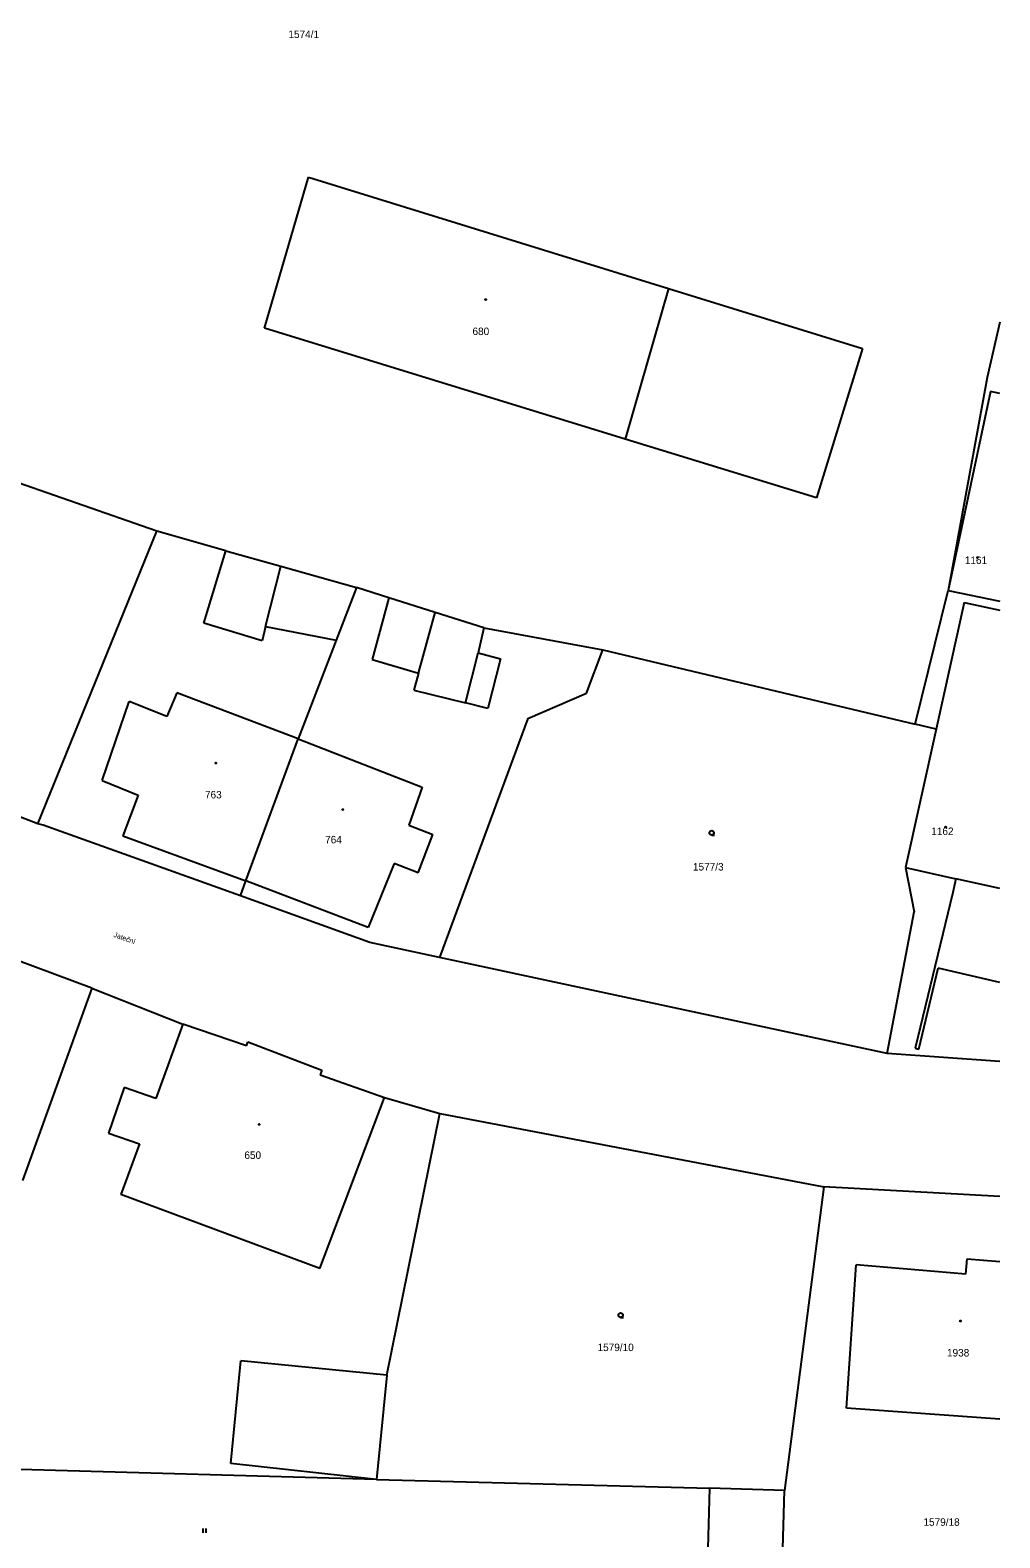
# Model space of a CAD drawing. Extents: x -866624 to -866276, y -1050208 to -1049940.
# Drawn here: x -866340.8 to -866276.1, y -1050100.7 to -1050000 of the extents above; entities that cross this region are included whole.
import ezdxf

# ---------------------------------------------------------------- set-up
doc = ezdxf.new("R2010")
doc.units = 0
for name, color, linetype in [('Default', 7, 'Continuous'), ('Hranice', 7, 'Continuous'), ('Hranice další', 7, 'Continuous'), ('Hranice-budov', 7, 'Continuous'), ('nazvy-ulic-tok', 7, 'Continuous'), ('Parcela-pozemkova', 7, 'Continuous'), ('Parcela-stavebni', 7, 'Continuous'), ('znacky-budov', 7, 'Continuous'), ('Znacky-kultury', 7, 'Continuous')]:
    doc.layers.add(name, color=color, linetype=linetype)

# ---------------------------------------------------------------- blocks, each defined once
blk = doc.blocks.new('p_zahr')
at = {"layer": 'Default'}
blk.add_line((0, -0.75), (0.99, -0.75), dxfattribs=at)
blk.add_circle((0, 0), 0.75, dxfattribs=at)
blk = doc.blocks.new('p_louka')
at = {"layer": 'Default'}
for p, q in [((-0.47, 0.72), (-0.47, -0.78)), ((0.53, 0.72), (0.53, -0.78))]:
    blk.add_line(p, q, dxfattribs=at)
blk = doc.blocks.new('s_zdena')
at = {"layer": 'Default'}
blk.add_circle((0, 0), 0.175, dxfattribs=at)
for start, end in [(0, 180), (180, 0)]:
    blk.add_arc((0, 0), 0.0875, start, end, dxfattribs=at)

msp = doc.modelspace()

# ---------------------------------------------------------------- linework, layer by layer
at = {"layer": 'Hranice'}
for p, q in [((-866325.18, -1050019.93), (-866322.25, -1050009.85)), ((-866322.25, -1050009.85), (-866298.21, -1050017.27)), ((-866298.21, -1050017.27), (-866285.24, -1050021.27)), ((-866276.08, -1050019.52), (-866276.93, -1050023.22)), ((-866301.1, -1050027.32), (-866325.18, -1050019.93)), ((-866285.24, -1050021.27), (-866288.32, -1050031.24)), ((-866276.93, -1050023.22), (-866279.54, -1050037.42)), ((-866276.7, -1050024.15), (-866279.54, -1050037.42)), ((-866276.08, -1050024.29), (-866276.7, -1050024.15)), ((-866332.37, -1050033.48), (-866353.36, -1050026.16)), ((-866288.32, -1050031.24), (-866301.1, -1050027.32)), ((-866340.32, -1050053.01), (-866332.37, -1050033.48)), ((-866327.75, -1050034.78), (-866332.37, -1050033.48)), ((-866327.75, -1050034.78), (-866324.08, -1050035.81)), ((-866324.08, -1050035.81), (-866319.04, -1050037.22)), ((-866319.04, -1050037.22), (-866320.39, -1050040.74)), ((-866316.88, -1050037.91), (-866319.04, -1050037.22)), ((-866313.78, -1050038.9), (-866316.88, -1050037.91)), ((-866281.73, -1050046.36), (-866279.54, -1050037.42)), ((-866279.54, -1050037.42), (-866276.08, -1050038.15)), ((-866310.54, -1050039.93), (-866313.78, -1050038.9)), ((-866278.47, -1050038.22), (-866280.34, -1050046.69)), ((-866278.47, -1050038.22), (-866276.08, -1050038.75)), ((-866310.54, -1050039.93), (-866302.58, -1050041.39)), ((-866320.39, -1050040.74), (-866322.93, -1050047.33)), ((-866303.67, -1050044.29), (-866302.58, -1050041.39)), ((-866302.58, -1050041.39), (-866281.73, -1050046.36)), ((-866307.59, -1050045.97), (-866303.67, -1050044.29)), ((-866340.32, -1050053.01), (-866360.48, -1050045.22)), ((-866307.59, -1050045.97), (-866313.5, -1050061.92)), ((-866280.34, -1050046.69), (-866282.38, -1050055.92)), ((-866280.34, -1050046.69), (-866281.73, -1050046.36)), ((-866326.42, -1050056.82), (-866322.93, -1050047.33)), ((-866339.95, -1050053.1), (-866340.32, -1050053.01)), ((-866326.78, -1050057.8), (-866339.95, -1050053.1)), ((-866282.38, -1050055.92), (-866281.8, -1050058.88)), ((-866282.38, -1050055.92), (-866279.01, -1050056.67)), ((-866326.78, -1050057.8), (-866326.42, -1050056.82)), ((-866279.01, -1050056.67), (-866279.23, -1050057.59)), ((-866336.71, -1050063.98), (-866355.25, -1050057.08)), ((-866318.15, -1050060.92), (-866326.78, -1050057.8)), ((-866279.23, -1050057.59), (-866281.74, -1050067.99)), ((-866283.6, -1050068.33), (-866281.8, -1050058.88)), ((-866313.5, -1050061.92), (-866318.15, -1050060.92)), ((-866283.6, -1050068.33), (-866313.5, -1050061.92)), ((-866281.5, -1050068.05), (-866280.2, -1050062.65)), ((-866276.08, -1050063.6), (-866280.2, -1050062.65)), ((-866336.71, -1050063.98), (-866341.33, -1050076.81)), ((-866336.71, -1050063.98), (-866330.62, -1050066.38)), ((-866326.38, -1050067.82), (-866330.62, -1050066.38)), ((-866326.38, -1050067.82), (-866326.3, -1050067.55)), ((-866326.3, -1050067.55), (-866321.35, -1050069.44)), ((-866281.74, -1050067.99), (-866281.5, -1050068.05)), ((-866276.08, -1050068.87), (-866283.6, -1050068.33)), ((-866321.35, -1050069.44), (-866321.45, -1050069.76)), ((-866321.45, -1050069.76), (-866317.17, -1050071.27)), ((-866317.17, -1050071.27), (-866313.48, -1050072.34)), ((-866317, -1050089.8), (-866313.48, -1050072.34)), ((-866313.48, -1050072.34), (-866287.84, -1050077.23)), ((-866287.84, -1050077.23), (-866290.46, -1050097.5)), ((-866276.08, -1050077.88), (-866287.84, -1050077.23)), ((-866278.35, -1050083.06), (-866278.27, -1050082.05)), ((-866278.27, -1050082.05), (-866276.08, -1050082.21)), ((-866286.31, -1050092), (-866285.68, -1050082.45)), ((-866278.35, -1050083.06), (-866285.68, -1050082.45)), ((-866317, -1050089.8), (-866317.7, -1050096.76)), ((-866276.08, -1050092.75), (-866286.31, -1050092)), ((-866317.7, -1050096.76), (-866346.74, -1050095.97)), ((-866317.7, -1050096.76), (-866295.47, -1050097.36)), ((-866295.47, -1050097.36), (-866295.74, -1050106.73)), ((-866290.46, -1050097.5), (-866295.47, -1050097.36)), ((-866290.72, -1050106.06), (-866290.46, -1050097.5))]:
    msp.add_line(p, q, dxfattribs=at)
at = {"layer": 'Hranice další'}
for p, q in [((-866298.21, -1050017.27), (-866301.1, -1050027.32)), ((-866329.23, -1050039.6), (-866327.75, -1050034.78)), ((-866325.1, -1050039.83), (-866324.08, -1050035.81)), ((-866316.88, -1050037.91), (-866318, -1050042.04)), ((-866314.9, -1050042.95), (-866313.78, -1050038.9)), ((-866325.34, -1050040.8), (-866329.23, -1050039.6)), ((-866325.1, -1050039.83), (-866325.34, -1050040.8)), ((-866325.1, -1050039.83), (-866320.39, -1050040.74)), ((-866310.54, -1050039.93), (-866310.92, -1050041.6)), ((-866311.76, -1050044.93), (-866310.92, -1050041.6)), ((-866310.92, -1050041.6), (-866309.42, -1050041.98)), ((-866318, -1050042.04), (-866314.9, -1050042.95)), ((-866314.9, -1050042.95), (-866315.21, -1050044.08)), ((-866309.42, -1050041.98), (-866310.26, -1050045.31)), ((-866336.01, -1050050.11), (-866334.21, -1050044.85)), ((-866331.69, -1050045.85), (-866334.21, -1050044.85)), ((-866331.02, -1050044.27), (-866331.69, -1050045.85)), ((-866322.93, -1050047.33), (-866331.02, -1050044.27)), ((-866315.21, -1050044.08), (-866311.76, -1050044.93)), ((-866310.26, -1050045.31), (-866311.76, -1050044.93)), ((-866322.93, -1050047.33), (-866314.65, -1050050.55)), ((-866336.01, -1050050.11), (-866333.62, -1050051.1)), ((-866314.65, -1050050.55), (-866315.55, -1050053.09)), ((-866333.62, -1050051.1), (-866334.63, -1050053.8)), ((-866334.63, -1050053.8), (-866326.42, -1050056.82)), ((-866315.55, -1050053.09), (-866313.93, -1050053.72)), ((-866314.91, -1050056.27), (-866313.93, -1050053.72)), ((-866316.52, -1050055.65), (-866318.26, -1050059.92)), ((-866314.91, -1050056.27), (-866316.52, -1050055.65)), ((-866318.26, -1050059.92), (-866326.42, -1050056.82)), ((-866276.08, -1050057.32), (-866279.01, -1050056.67)), ((-866330.62, -1050066.38), (-866332.43, -1050071.34)), ((-866334.55, -1050070.61), (-866335.59, -1050073.65)), ((-866332.43, -1050071.34), (-866334.55, -1050070.61)), ((-866321.48, -1050082.69), (-866317.17, -1050071.27)), ((-866335.59, -1050073.65), (-866333.53, -1050074.36)), ((-866333.53, -1050074.36), (-866334.76, -1050077.74)), ((-866321.48, -1050082.69), (-866334.76, -1050077.74)), ((-866327.43, -1050095.7), (-866326.75, -1050088.84)), ((-866317, -1050089.8), (-866326.75, -1050088.84)), ((-866317.7, -1050096.76), (-866327.43, -1050095.7))]:
    msp.add_line(p, q, dxfattribs=at)
at = {"layer": 'Hranice-budov'}
for p, q in [((-866325.18, -1050019.93), (-866322.25, -1050009.85)), ((-866322.25, -1050009.85), (-866298.21, -1050017.27)), ((-866298.21, -1050017.27), (-866301.1, -1050027.32)), ((-866301.1, -1050027.32), (-866325.18, -1050019.93)), ((-866276.7, -1050024.15), (-866279.54, -1050037.42)), ((-866276.08, -1050024.29), (-866276.7, -1050024.15)), ((-866279.54, -1050037.42), (-866276.08, -1050038.15)), ((-866278.47, -1050038.22), (-866280.34, -1050046.69)), ((-866278.47, -1050038.22), (-866276.08, -1050038.75)), ((-866336.01, -1050050.11), (-866334.21, -1050044.85)), ((-866331.69, -1050045.85), (-866334.21, -1050044.85)), ((-866331.02, -1050044.27), (-866331.69, -1050045.85)), ((-866322.93, -1050047.33), (-866331.02, -1050044.27)), ((-866280.34, -1050046.69), (-866282.38, -1050055.92)), ((-866326.42, -1050056.82), (-866322.93, -1050047.33)), ((-866326.42, -1050056.82), (-866322.93, -1050047.33)), ((-866322.93, -1050047.33), (-866314.65, -1050050.55)), ((-866336.01, -1050050.11), (-866333.62, -1050051.1)), ((-866314.65, -1050050.55), (-866315.55, -1050053.09)), ((-866333.62, -1050051.1), (-866334.63, -1050053.8)), ((-866334.63, -1050053.8), (-866326.42, -1050056.82)), ((-866315.55, -1050053.09), (-866313.93, -1050053.72)), ((-866314.91, -1050056.27), (-866313.93, -1050053.72)), ((-866316.52, -1050055.65), (-866318.26, -1050059.92)), ((-866314.91, -1050056.27), (-866316.52, -1050055.65)), ((-866282.38, -1050055.92), (-866279.01, -1050056.67)), ((-866318.26, -1050059.92), (-866326.42, -1050056.82)), ((-866276.08, -1050057.32), (-866279.01, -1050056.67)), ((-866330.62, -1050066.38), (-866332.43, -1050071.34)), ((-866326.38, -1050067.82), (-866330.62, -1050066.38)), ((-866326.38, -1050067.82), (-866326.3, -1050067.55)), ((-866326.3, -1050067.55), (-866321.35, -1050069.44)), ((-866321.35, -1050069.44), (-866321.45, -1050069.76)), ((-866321.45, -1050069.76), (-866317.17, -1050071.27)), ((-866334.55, -1050070.61), (-866335.59, -1050073.65)), ((-866332.43, -1050071.34), (-866334.55, -1050070.61)), ((-866321.48, -1050082.69), (-866317.17, -1050071.27)), ((-866335.59, -1050073.65), (-866333.53, -1050074.36)), ((-866333.53, -1050074.36), (-866334.76, -1050077.74)), ((-866321.48, -1050082.69), (-866334.76, -1050077.74)), ((-866278.35, -1050083.06), (-866278.27, -1050082.05)), ((-866278.27, -1050082.05), (-866276.08, -1050082.21)), ((-866286.31, -1050092), (-866285.68, -1050082.45)), ((-866278.35, -1050083.06), (-866285.68, -1050082.45)), ((-866276.08, -1050092.75), (-866286.31, -1050092))]:
    msp.add_line(p, q, dxfattribs=at)

# ---------------------------------------------------------------- block references
at = {"layer": 'znacky-budov', "xscale": 0.2, "yscale": 0.20000000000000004}
for p in [(-866310.41, -1050018.01), (-866277.57, -1050035.23), (-866328.43, -1050048.95), (-866319.94, -1050052.05), (-866279.7, -1050053.22), (-866325.54, -1050073.07), (-866278.71, -1050086.19)]:
    msp.add_blockref('s_zdena', p, dxfattribs=at)
at = {"layer": 'Znacky-kultury', "xscale": 0.2, "yscale": 0.20000000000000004}
for name, p in [('p_zahr', (-866295.32, -1050053.61)), ('p_zahr', (-866301.4, -1050085.8)), ('p_louka', (-866329.19, -1050100.18))]:
    msp.add_blockref(name, p, dxfattribs=at)

# ---------------------------------------------------------------- texts
at = {"layer": 'nazvy-ulic-tok'}
msp.add_text('Jateční', height=0.34, rotation=340.3108, dxfattribs=at).set_placement((-866335.29, -1050060.54))
at = {"layer": 'Parcela-pozemkova'}
for s, p in [('1574/1', (-866323.58, -1050000.55)), ('1577/3', (-866296.57, -1050056.12)), ('1579/10', (-866302.94, -1050088.2)), ('1579/18', (-866281.18, -1050099.86))]:
    msp.add_text(s, height=0.5, dxfattribs=at).set_placement(p)
at = {"layer": 'Parcela-stavebni'}
for s, p in [('680', (-866311.29, -1050020.38)), ('1161', (-866278.42, -1050035.66)), ('763', (-866329.15, -1050051.31)), ('764', (-866321.13, -1050054.31)), ('1162', (-866280.66, -1050053.75)), ('650', (-866326.52, -1050075.37)), ('1938', (-866279.61, -1050088.56))]:
    msp.add_text(s, height=0.5, dxfattribs=at).set_placement(p)

doc.saveas('drawing.dxf')
